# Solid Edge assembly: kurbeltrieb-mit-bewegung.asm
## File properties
Author: helmut
Template: Normal.asm
Last saved by: helmut
Revision: 2
Application: Solid Edge
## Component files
Grundkoerper.par
Schieber.par
Drehscheibe.par
Hebel.par
Stufenbolzen.par
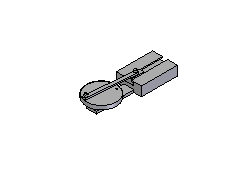
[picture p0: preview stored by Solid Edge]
